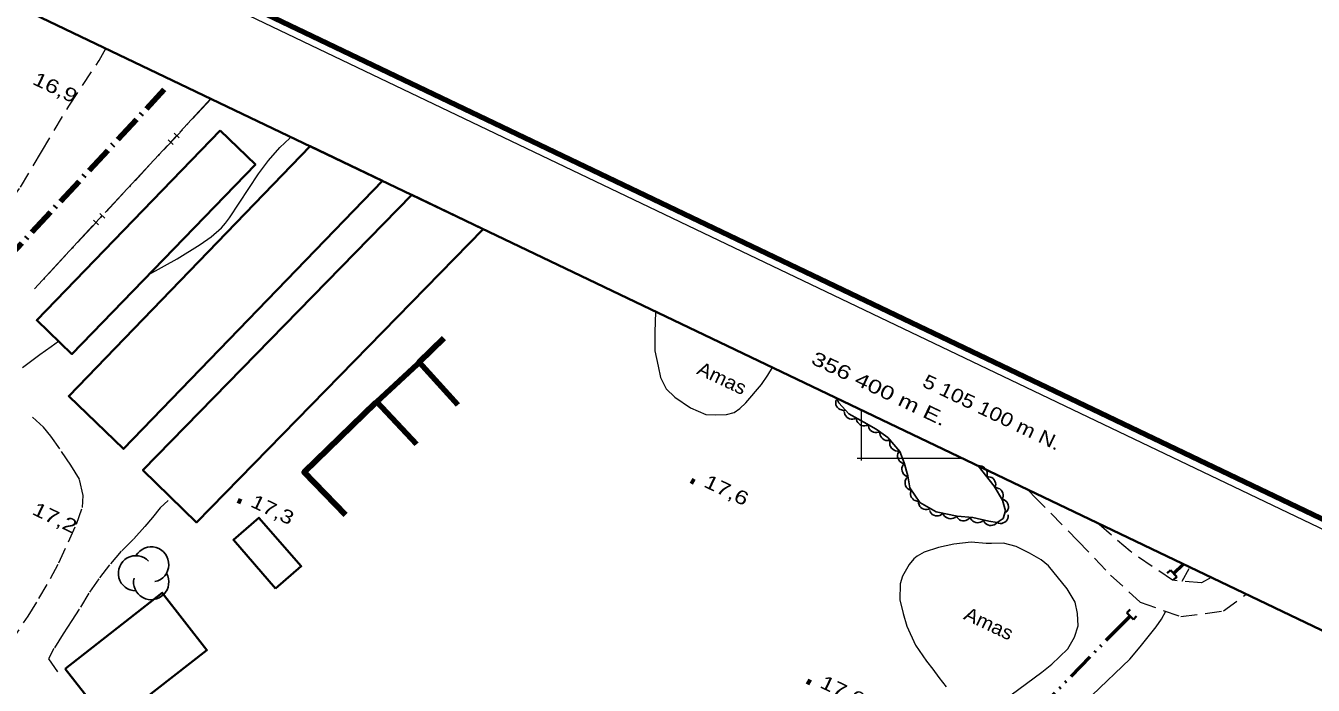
# Model space of a CAD drawing. Extents: x 355726 to 357533, y 5103782 to 5105258.
# Drawn here: x 356308.4 to 356449.5, y 5105075.2 to 5105147.4 of the extents above; entities that cross this region are included whole.
import ezdxf
from ezdxf.enums import TextEntityAlignment as Align

# ---------------------------------------------------------------- set-up
doc = ezdxf.new("R2010")
doc.units = 0
doc.header["$LTSCALE"] = 0.6
for name, pattern in [('DASH_DOUBLE_DOT', [9.2, 5, -1.2, 0.3, -1.2, 0.3, -1.2]), ('DOT_DASHED', [7.7, 5, -1.2, 0.3, -1.2]), ('LONG_DASH_SHORT_DASH', [9.9, 6, -1.2, 1.5, -1.2]), ('LONG_DASHED', [7.5, 6, -1.5]), ('MEDIUM_DASHED', [4.5, 3, -1.5])]:
    doc.linetypes.add(name, pattern=pattern)
for name, color, linetype, lineweight in [('19', 7, 'Continuous', 13), ('2', 7, 'LONG_DASHED', 13), ('26', 7, 'Continuous', 35), ('3', 7, 'Continuous', 140), ('31', 7, 'Continuous', 35), ('37', 7, 'Continuous', 13), ('4', 7, 'DASH_DOUBLE_DOT', 53), ('41', 7, 'DOT_DASHED', 90), ('44', 7, 'Continuous', 25), ('57', 7, 'LONG_DASH_SHORT_DASH', 13), ('60', 7, 'Continuous', 13), ('61', 7, 'Continuous', 13)]:
    doc.layers.add(name, color=color, linetype=linetype, lineweight=lineweight)

msp = doc.modelspace()

# ---------------------------------------------------------------- linework, layer by layer
at = {"layer": '19', "linetype": 'MEDIUM_DASHED'}
for points in [[(356305.04, 5105125.99), (356307.87, 5105129.73), (356310.14, 5105133.62), (356313.14, 5105138.62), (356316.46, 5105143.61), (356317.22, 5105144.93)], [(356303.93, 5105077.18), (356304.01, 5105077.25), (356305.29, 5105078.37), (356306.68, 5105079.75), (356308.7, 5105082.72), (356309.87, 5105084.65), (356311.13, 5105086.84), (356312.04, 5105088.55), (356313.11, 5105090.86), (356313.98, 5105092.79), (356314.63, 5105094.63), (356314.72, 5105095.96), (356314.33, 5105097.74), (356313.36, 5105099.26), (356312.16, 5105101.05), (356311.17, 5105102.45), (356310.39, 5105103.42), (356309.17, 5105104.54)], [(356418.21, 5105096.59), (356418.84, 5105095.92), (356423.67, 5105091.03), (356427.29, 5105087.23), (356430.52, 5105084.26), (356434.99, 5105082.67), (356439.68, 5105083.3), (356442.14, 5105085.13)], [(356324.03, 5105095.41), (356323.14, 5105094.58), (356322.3, 5105093.55), (356321.46, 5105092.55), (356320.22, 5105091.17), (356318.9, 5105089.84), (356317.61, 5105088.33), (356316.43, 5105086.83), (356315.35, 5105085.25), (356314.27, 5105083.49), (356313.46, 5105082.24), (356312.53, 5105080.79), (356311.51, 5105079.17), (356310.93, 5105078.03), (356311.91, 5105076.62)], [(356438.32, 5105086.97), (356437.27, 5105086.36), (356434.06, 5105086.66), (356429.42, 5105089.83), (356425.85, 5105092.94)]]:
    msp.add_lwpolyline(points, dxfattribs=at)
at = {"layer": '2', "linetype": 'Continuous'}
msp.add_line((356435.15, 5105086.56), (356435.91, 5105087.94), dxfattribs=at)
for points in [[(356321.9, 5105120.15), (356325, 5105121.88), (356327.53, 5105123.44), (356328.76, 5105124.3), (356329.88, 5105125.3), (356330.33, 5105125.8), (356330.76, 5105126.38), (356333.93, 5105131.19), (356335.03, 5105132.68), (356336.25, 5105134.07), (356337.35, 5105135.12)], [(356308.08, 5105109.96), (356309.96, 5105111.4), (356311.23, 5105112.26), (356312.01, 5105112.86)], [(356425.28, 5105074.07), (356429.39, 5105078.01), (356430.54, 5105079.35), (356432.27, 5105081.55), (356432.86, 5105082.41), (356433.33, 5105083.26)]]:
    msp.add_lwpolyline(points, dxfattribs=at)
at = {"layer": '26'}
for p, q in [((356433.84, 5105087.78), (356433.5, 5105087.42)), ((356433.84, 5105087.78), (356434.55, 5105087.05)), ((356434.55, 5105087.05), (356434.19, 5105086.71)), ((356429.08, 5105083.1), (356429.44, 5105083.44)), ((356429.79, 5105082.37), (356429.08, 5105083.1)), ((356429.79, 5105082.37), (356430.14, 5105082.73))]:
    msp.add_line(p, q, dxfattribs=at)
at = {"layer": '3'}
for p, q in [((356381.32, 5105097.58), (356381.68, 5105097.41)), ((356331.66, 5105095.41), (356332.02, 5105095.24)), ((356394.04, 5105075.6), (356394.4, 5105075.43))]:
    msp.add_line(p, q, dxfattribs=at)
at = {"layer": '31'}
for points in [[(356329.74, 5105135.96), (356309.63, 5105115.16), (356313.48, 5105111.44), (356333.59, 5105132.24), (356329.74, 5105135.96)], [(356339.59, 5105134.23), (356347.52, 5105130.43), (356319.14, 5105101.05), (356313.14, 5105106.84)], [(356350.72, 5105128.9), (356358.55, 5105125.15), (356327.14, 5105093), (356321.26, 5105098.74)], [(356335.81, 5105085.75), (356331.18, 5105091.08), (356333.98, 5105093.51), (356338.61, 5105088.19), (356335.81, 5105085.75)], [(356312.74, 5105076.96), (356323.38, 5105085.28), (356328.28, 5105079.01), (356317.63, 5105070.7), (356312.74, 5105076.96)]]:
    msp.add_lwpolyline(points, close=True, dxfattribs=at)
at = {"layer": '37', "linetype": 'DOT_DASHED', "lineweight": 25}
msp.add_line((356328.73, 5105139.42), (356309.39, 5105118.59), dxfattribs=at)
at = {"layer": '37', "lineweight": 25}
for p, q in [((356328.71, 5105139.44), (356325.31, 5105135.78)), ((356325.25, 5105135.15), (356324.7, 5105135.66)), ((356323.95, 5105134.31), (356320.55, 5105130.65)), ((356324.57, 5105134.42), (356324.02, 5105134.93)), ((356324.97, 5105135.41), (356324.29, 5105134.68)), ((356320.55, 5105130.65), (356317.14, 5105126.98)), ((356316.4, 5105125.62), (356315.85, 5105126.13)), ((356316.8, 5105126.62), (356316.12, 5105125.88)), ((356317.08, 5105126.36), (356316.53, 5105126.87)), ((356315.78, 5105125.52), (356312.38, 5105121.85)), ((356312.38, 5105121.85), (356309.37, 5105118.61))]:
    msp.add_line(p, q, dxfattribs=at)
at = {"layer": '37', "lineweight": 90}
for p, q in [((356351.55, 5105110.55), (356355.76, 5105105.89)), ((356346.88, 5105106.2), (356351.25, 5105101.59))]:
    msp.add_line(p, q, dxfattribs=at)
msp.add_lwpolyline([(356343.45, 5105093.83), (356338.93, 5105098.5), (356346.76, 5105106.09), (356346.88, 5105106.2), (356351.34, 5105110.35), (356351.55, 5105110.55), (356354.23, 5105113.19)], dxfattribs=at)
at = {"layer": '4'}
msp.add_line((356434.2, 5105087.41), (356435.25, 5105088.42), dxfattribs=at)
msp.add_lwpolyline([(356419.11, 5105072.16), (356427.79, 5105081.09), (356429.44, 5105082.74)], dxfattribs=at)
at = {"layer": '41'}
msp.add_line((356268.25, 5105080.75), (356323.61, 5105140.45), dxfattribs=at)
at = {"layer": '44'}
for points in [[(356398.22, 5105105.31), (356398.02, 5105105.28), (356397.82, 5105105.32), (356397.66, 5105105.36), (356397.51, 5105105.46), (356397.37, 5105105.58), (356397.27, 5105105.74), (356397.2, 5105105.89), (356397.17, 5105106.06), (356397.17, 5105106.25), (356397.21, 5105106.42)], [(356399.42, 5105104.44), (356399.23, 5105104.35), (356399.03, 5105104.31), (356398.87, 5105104.31), (356398.7, 5105104.35), (356398.53, 5105104.43), (356398.38, 5105104.55), (356398.27, 5105104.66), (356398.18, 5105104.82), (356398.13, 5105104.99), (356398.11, 5105105.17)], [(356400.73, 5105103.71), (356400.55, 5105103.62), (356400.34, 5105103.58), (356400.18, 5105103.58), (356400.01, 5105103.62), (356399.84, 5105103.7), (356399.69, 5105103.82), (356399.58, 5105103.93), (356399.49, 5105104.09), (356399.44, 5105104.26), (356399.42, 5105104.44)], [(356402.04, 5105102.98), (356401.85, 5105102.89), (356401.65, 5105102.85), (356401.49, 5105102.84), (356401.32, 5105102.89), (356401.15, 5105102.96), (356401, 5105103.08), (356400.89, 5105103.2), (356400.8, 5105103.36), (356400.75, 5105103.53), (356400.73, 5105103.71)], [(356403.23, 5105102.06), (356403.03, 5105101.99), (356402.83, 5105101.97), (356402.67, 5105101.99), (356402.5, 5105102.05), (356402.34, 5105102.14), (356402.21, 5105102.28), (356402.11, 5105102.41), (356402.04, 5105102.57), (356402.01, 5105102.75), (356402.01, 5105102.93)], [(356404.13, 5105100.84), (356403.92, 5105100.82), (356403.72, 5105100.85), (356403.57, 5105100.91), (356403.42, 5105101.01), (356403.29, 5105101.14), (356403.19, 5105101.3), (356403.12, 5105101.45), (356403.1, 5105101.62), (356403.11, 5105101.81), (356403.16, 5105101.98)], [(356404.7, 5105099.45), (356404.49, 5105099.5), (356404.32, 5105099.6), (356404.18, 5105099.7), (356404.08, 5105099.85), (356404, 5105100.01), (356403.96, 5105100.2), (356403.95, 5105100.36), (356403.99, 5105100.53), (356404.05, 5105100.71), (356404.16, 5105100.85)], [(356405.09, 5105098.01), (356404.89, 5105098.07), (356404.73, 5105098.19), (356404.6, 5105098.3), (356404.52, 5105098.46), (356404.45, 5105098.63), (356404.43, 5105098.82), (356404.43, 5105098.98), (356404.49, 5105099.15), (356404.57, 5105099.32), (356404.69, 5105099.45)], [(356412.78, 5105099.18), (356412.99, 5105099.19), (356413.19, 5105099.15), (356413.34, 5105099.09), (356413.48, 5105098.99), (356413.61, 5105098.85), (356413.7, 5105098.68), (356413.76, 5105098.53), (356413.78, 5105098.36), (356413.76, 5105098.17), (356413.71, 5105098)], [(356405.36, 5105096.53), (356405.17, 5105096.61), (356405.01, 5105096.75), (356404.9, 5105096.87), (356404.82, 5105097.03), (356404.77, 5105097.2), (356404.77, 5105097.4), (356404.79, 5105097.56), (356404.85, 5105097.72), (356404.95, 5105097.88), (356405.08, 5105098)], [(356413.71, 5105098), (356413.91, 5105098.01), (356414.11, 5105097.97), (356414.27, 5105097.91), (356414.41, 5105097.8), (356414.53, 5105097.67), (356414.62, 5105097.5), (356414.69, 5105097.35), (356414.7, 5105097.18), (356414.69, 5105096.99), (356414.63, 5105096.82)], [(356406.29, 5105095.33), (356406.08, 5105095.33), (356405.89, 5105095.39), (356405.74, 5105095.45), (356405.61, 5105095.57), (356405.49, 5105095.71), (356405.41, 5105095.89), (356405.36, 5105096.04), (356405.36, 5105096.22), (356405.39, 5105096.4), (356405.45, 5105096.57)], [(356414.61, 5105096.81), (356414.82, 5105096.8), (356415.01, 5105096.73), (356415.16, 5105096.66), (356415.29, 5105096.53), (356415.4, 5105096.39), (356415.47, 5105096.21), (356415.52, 5105096.05), (356415.51, 5105095.88), (356415.47, 5105095.69), (356415.4, 5105095.53)], [(356407.54, 5105094.53), (356407.36, 5105094.44), (356407.16, 5105094.4), (356406.99, 5105094.4), (356406.82, 5105094.44), (356406.65, 5105094.52), (356406.5, 5105094.64), (356406.39, 5105094.75), (356406.31, 5105094.91), (356406.25, 5105095.09), (356406.24, 5105095.27)], [(356415.42, 5105095.54), (356415.62, 5105095.47), (356415.79, 5105095.36), (356415.91, 5105095.25), (356416, 5105095.09), (356416.06, 5105094.92), (356416.09, 5105094.73), (356416.09, 5105094.57), (356416.03, 5105094.4), (356415.95, 5105094.23), (356415.83, 5105094.1)], [(356408.93, 5105094.01), (356408.78, 5105093.87), (356408.6, 5105093.77), (356408.45, 5105093.72), (356408.27, 5105093.71), (356408.09, 5105093.73), (356407.91, 5105093.8), (356407.76, 5105093.88), (356407.64, 5105094.01), (356407.53, 5105094.16), (356407.47, 5105094.32)], [(356410.4, 5105093.7), (356410.25, 5105093.55), (356410.07, 5105093.46), (356409.91, 5105093.41), (356409.74, 5105093.4), (356409.55, 5105093.42), (356409.38, 5105093.49), (356409.23, 5105093.57), (356409.11, 5105093.69), (356409, 5105093.84), (356408.93, 5105094.01)], [(356411.89, 5105093.55), (356411.76, 5105093.39), (356411.59, 5105093.27), (356411.44, 5105093.2), (356411.27, 5105093.17), (356411.08, 5105093.17), (356410.9, 5105093.22), (356410.75, 5105093.28), (356410.61, 5105093.39), (356410.48, 5105093.53), (356410.4, 5105093.69)], [(356413.36, 5105093.26), (356413.21, 5105093.11), (356413.03, 5105093.02), (356412.87, 5105092.97), (356412.7, 5105092.96), (356412.51, 5105092.99), (356412.34, 5105093.06), (356412.19, 5105093.14), (356412.07, 5105093.26), (356411.96, 5105093.42), (356411.9, 5105093.58)], [(356414.84, 5105093), (356414.7, 5105092.85), (356414.52, 5105092.74), (356414.37, 5105092.68), (356414.2, 5105092.66), (356414.01, 5105092.67), (356413.83, 5105092.73), (356413.68, 5105092.79), (356413.55, 5105092.91), (356413.43, 5105093.05), (356413.35, 5105093.21)], [(356416.08, 5105093.83), (356416.08, 5105093.62), (356416.02, 5105093.43), (356415.96, 5105093.28), (356415.84, 5105093.14), (356415.7, 5105093.03), (356415.53, 5105092.95), (356415.37, 5105092.89), (356415.2, 5105092.89), (356415.01, 5105092.92), (356414.84, 5105092.98)]]:
    msp.add_lwpolyline(points, dxfattribs=at)
at = {"layer": '44', "linetype": 'DOT_DASHED'}
msp.add_lwpolyline([(356412.78, 5105099.18), (356414.52, 5105096.96), (356415.45, 5105095.45), (356415.78, 5105094.28), (356415.51, 5105093.44), (356414.87, 5105093), (356413.94, 5105093.13), (356412.18, 5105093.52), (356410.49, 5105093.68), (356408.19, 5105094.17), (356406.39, 5105095.18), (356405.31, 5105096.78), (356405.06, 5105098.11), (356404.67, 5105099.52), (356404.19, 5105100.77), (356402.88, 5105102.31), (356401.61, 5105103.22), (356400.25, 5105103.98), (356398.6, 5105104.9), (356397.5, 5105106.11), (356397.25, 5105106.61)], dxfattribs=at)
at = {"layer": '44'}
for centre, start, end in [((356322.17, 5105088.39), 282.2692, 149.7263), ((356320.5, 5105087.42), 44.1154, 269.804), ((356322.17, 5105086.46), 166.9369, 29.6212)]:
    msp.add_arc(centre, 1.93, start, end, dxfattribs=at)
at = {"layer": '57'}
for points in [[(356377.43, 5105116.09), (356377.43, 5105116.07), (356377.36, 5105113.83), (356377.36, 5105111.79), (356377.71, 5105110.12), (356377.99, 5105108.87), (356378.59, 5105107.64), (356379.55, 5105106.71), (356381.27, 5105105.54), (356382.93, 5105104.81), (356384.02, 5105104.8), (356385.22, 5105104.82), (356386.04, 5105105.05), (356386.68, 5105105.48), (356387.33, 5105106.11), (356389.05, 5105108.11), (356389.72, 5105109.12), (356390.24, 5105109.96)], [(356416.39, 5105074.11), (356418.08, 5105075.35), (356419.76, 5105076.58), (356420.85, 5105077.45), (356421.7, 5105078.26), (356422.6, 5105079.15), (356423.32, 5105080.43), (356423.73, 5105081.68), (356423.68, 5105083), (356423.4, 5105084.25), (356422.54, 5105085.72), (356420.5, 5105088.25), (356419.68, 5105088.9), (356418.4, 5105089.62), (356416.93, 5105090.35), (356415.56, 5105090.72), (356414.24, 5105090.67), (356413.66, 5105090.7), (356412.03, 5105090.82), (356410.12, 5105090.6), (356408.44, 5105090.25), (356406.87, 5105089.75), (356406.11, 5105089.28), (356405.75, 5105088.99), (356405.21, 5105088.4), (356404.49, 5105087.12), (356404.22, 5105086.28), (356404.21, 5105084.51), (356404.56, 5105083.02), (356404.95, 5105081.61), (356405.92, 5105079.54), (356407.11, 5105077.78), (356407.8, 5105076.9), (356408.49, 5105076.01), (356409.29, 5105074.97)]]:
    msp.add_lwpolyline(points, dxfattribs=at)
at = {"layer": '60', "lineweight": 158}
msp.add_lwpolyline([(355725.74, 5104464.62), (357152.72, 5103781.6), (357532.66, 5104575.38), (356105.68, 5105258.4)], close=True, dxfattribs=at)
at = {"layer": '60'}
msp.add_lwpolyline([(355727.1, 5104465.08), (357152.24, 5103782.93), (357531.32, 5104574.91), (356106.18, 5105257.06)], close=True, dxfattribs=at)
at = {"layer": '60', "lineweight": 35}
msp.add_lwpolyline([(355740.43, 5104469.78), (356913.03, 5103908.53), (357283.46, 5104682.46), (356110.86, 5105243.71)], close=True, dxfattribs=at)
at = {"layer": '61'}
for p, q in [((356400, 5105099.77), (356400, 5105105.31)), ((356411.1, 5105100), (356399.52, 5105100))]:
    msp.add_line(p, q, dxfattribs=at)

# ---------------------------------------------------------------- texts
at = {"layer": '3'}
for s, width, p in [('16,9   ', 1.3, (356309.05, 5105141.09)), ('17,6   ', 1.3, (356382.6, 5105096.96)), ('17,2   ', 1.3, (356309.01, 5105093.94)), ('17,3   ', 1.25, (356332.95, 5105094.78)), ('17,6   ', 1.3, (356395.33, 5105074.96))]:
    msp.add_text(s, height=1.5, rotation=334.423, dxfattribs=dict(at, width=width)).set_placement(p)
at = {"layer": '57', "width": 1.1}
for p in [(356381.85, 5105109.33), (356411.08, 5105082.44)]:
    msp.add_text('Amas', height=1.5, rotation=334.72, dxfattribs=at).set_placement(p)
at = {"layer": '61'}
for s, width, p in [(' 356 400 m E.', 1.35, (356401.28, 5105107.14)), (' 5 105 100 m N.', 1.2, (356413.67, 5105104.54))]:
    msp.add_text(s, height=1.5, rotation=334.42, dxfattribs=dict(at, width=width)).set_placement(p, align=Align.CENTER)

doc.saveas('drawing.dxf')
